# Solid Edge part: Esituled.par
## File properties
Author: Türk
Template: iso part.par
Last saved by: Türk
Revision: 14
Application: Solid Edge
Accuracy: 0,990
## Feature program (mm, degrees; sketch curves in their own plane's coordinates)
base feature "unnamed BaseFeature 1"
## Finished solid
Body 1: sheet body, 1 face, 20 edges, 20 vertices.
  Faces by surface: plane 1
  Edges by curve: line 14, spline 4, circle 2
Body 2: sheet body, 1 face, 20 edges, 20 vertices.
  Faces by surface: plane 1
  Edges by curve: line 14, spline 4, circle 2
Body 3: sheet body, 5 faces, 7 edges, 0 vertices.
  Faces by surface: plane 5
  Edges by curve: circle 7
Body 4: other body (type 2), 2 faces, 4 edges, 0 vertices.
  Faces by surface: plane 2
  Edges by curve: circle 4
Body 5: solid body, 20 faces, 18 edges, 4 vertices, 2 separate solids.
  Faces by surface: plane 8, cylinder 6, spun 4, torus 2
  Edges by curve: circle 18
Bounding box of the edges (mm; curved faces can reach further): 271.498 x 116.757 x 140.000, from (-579.1669, -761.7573, 95.798) to (-307.6693, -645, 235.798).
Cylindrical faces by radius (mm): R25 x2, R35 x1, R46.25 x1, R55 x1, R70 x1
Toroidal faces (ring radius, tube radius in mm): R41.25 r5 x1, R65 r5 x1
Planar faces by outward normal: +y 4, -y 4
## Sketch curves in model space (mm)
circle centre (-509.1669, -740, 165.798) radius 60
line (-509.1669, -650, 220.798) -> (-509.1669, -650, 110.798)
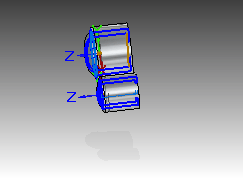
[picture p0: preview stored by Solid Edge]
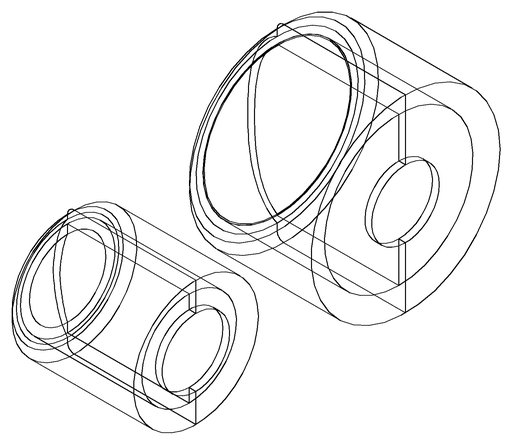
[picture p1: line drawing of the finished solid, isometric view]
